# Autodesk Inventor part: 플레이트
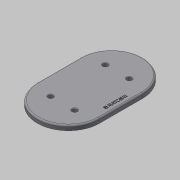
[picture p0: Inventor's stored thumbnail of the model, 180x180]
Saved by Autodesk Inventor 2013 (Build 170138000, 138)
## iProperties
Created: 2016-08
Part Number: 플레이트
Material: 알루미늄 6061
Document SubType Name: Modeling
Designer: mduedu
Density: 2.71 g/cm^3
Mass: 665.114 g
Surface Area: 557.689 cm^2
Volume: 245.429 cm^3
Author: mduedu
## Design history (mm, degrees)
sketch "스케치1" dims "d0" = 220, "d2" = 130
  geometry: L1 (45, 65)-(-45, 65); L2 (-45, 65)-(-45, -65); L3 (-45, -65)-(45, -65); L4 (45, -65)-(45, 65); L5 (45, 65)-(-45, -65); L6 (-45, 65)-(45, -65); 5 further points
  constraints: 12 end point, 5 midpoint, 2 parallel, 2 vertical alignment, 1 coincident, 1 horizontal, 1 perpendicular, 4 other
extrude "돌출1" new body sketch "스케치1" distance "d3" = 10; taper "d4" = 0 deg
sketch "스케치2"
  geometry: L1 (-57, -25)-(57, -25); L2 (57, -25)-(57, 25); L3 (57, 25)-(-57, 25); L4 (-57, 25)-(-57, -25); L5 (-57, -25)-(57, 25); L6 (57, -25)-(-57, 25); C1 r 5 at (-57, 25); C2 r 5 at (57, 25); C3 r 5 at (57, -25); C4 r 5 at (-57, -25); 1 further point
  constraints: 12 end point, 4 centre point, 4 coincident, 3 equal radius, 2 midpoint, 2 parallel, 1 horizontal, 1 perpendicular
  dimensions: "d5" = 114 distance of L2.end L3.end; "d7" = 50 distance of L1.end L2.end; "d8" = 10 diameter of C1
extrude "돌출2" cut sketch "스케치2" stored distance "d9" = 10; taper "d10" = 0 deg
chamfer "모따기1" distance "d11" = 1; stored, may be unused: second distance "d12" = 2, angle "d13" = 45 deg
fillet "모깎기1" dims "d14" = 3
sketch "스케치3"
  geometry: L1 (-45, -65)-(45, -65) reference; 2 further points
  constraints: 1 vertical alignment, 1 other
  dimensions: "d15" = 12 distance from line of point (0, -53) L1
feature "엠보싱1" sketch "스케치3" dims "d16" = 0.5, "d17" = 0
node "솔리드1"
